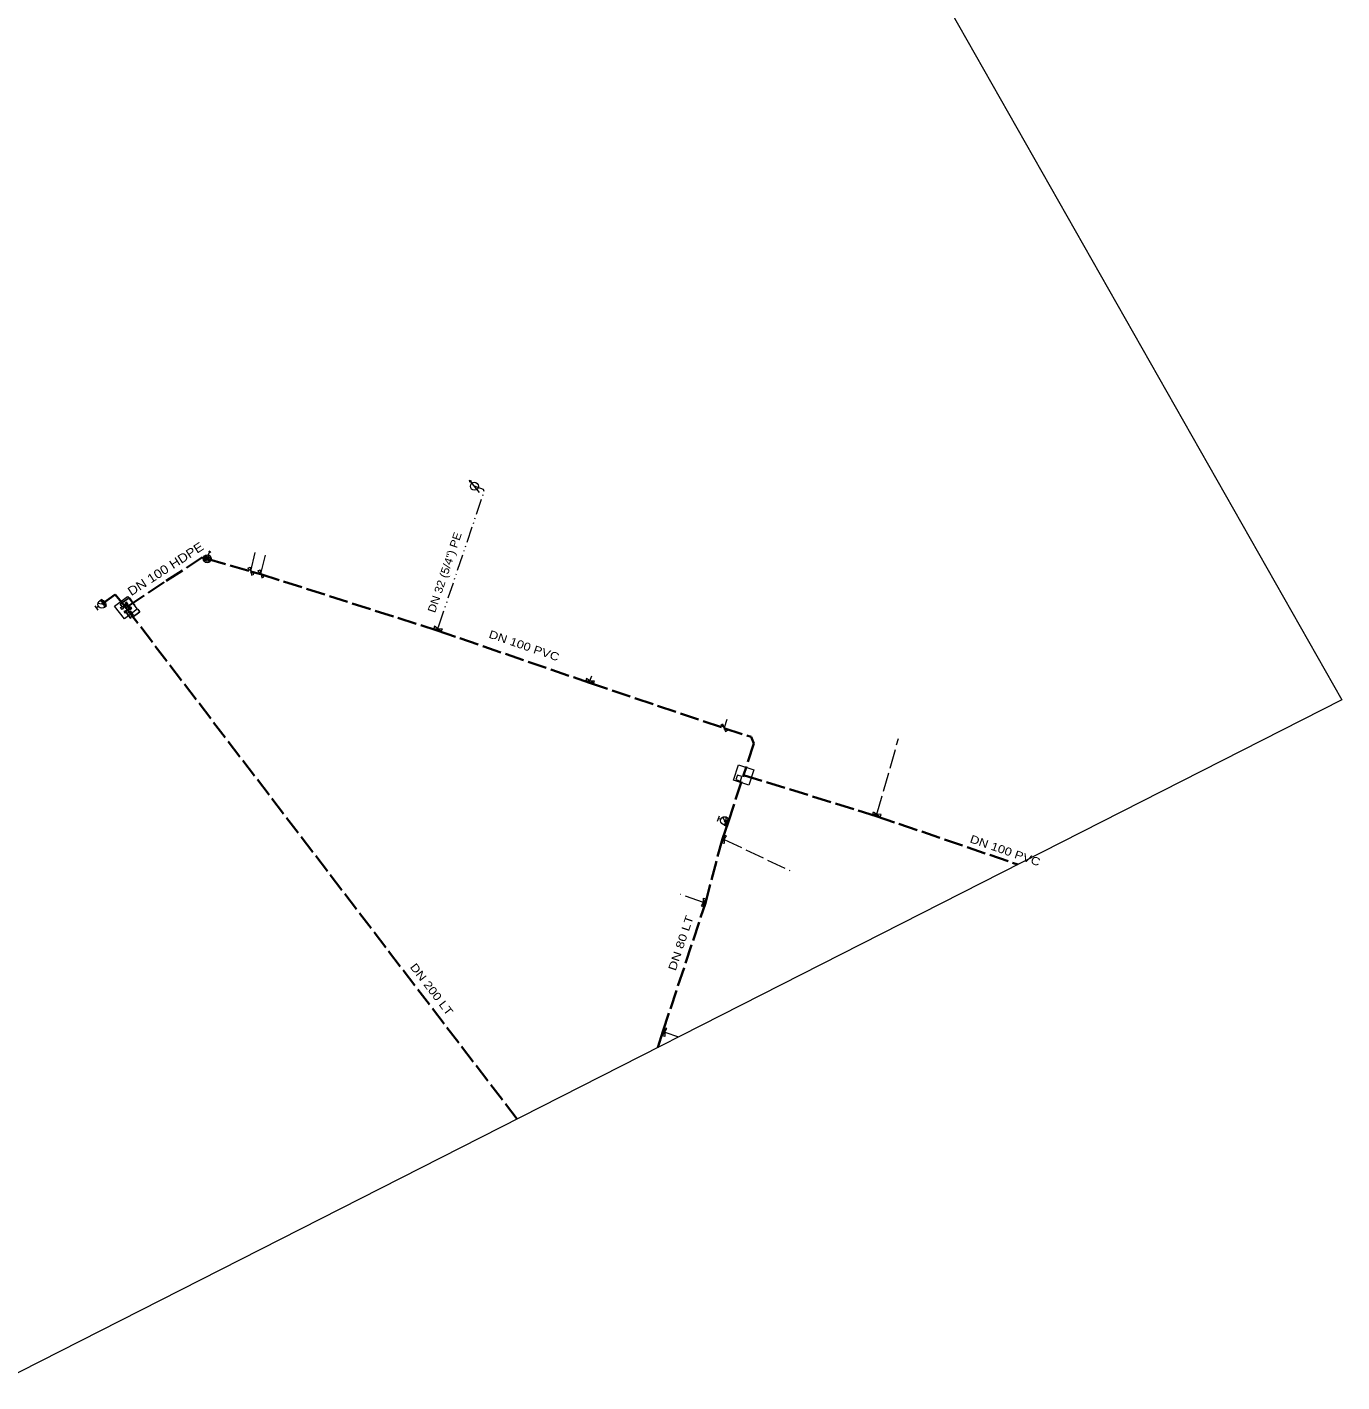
# Model space of a CAD drawing. Extents: x -666776 to -665461, y -1035476 to -1034122.
# Drawn here: x -665625.7 to -665461.4, y -1035475.8 to -1035306.5 of the extents above; entities that cross this region are included whole.
import ezdxf
from ezdxf.enums import TextEntityAlignment as Align

# ---------------------------------------------------------------- set-up
doc = ezdxf.new("R2010")
doc.units = 0
doc.header["$LTSCALE"] = 0.4
for name, pattern in [('DASH_DOUBLE_DOT', [9.2, 5, -1.2, 0.3, -1.2, 0.3, -1.2]), ('LONG_DASHED', [7.5, 6, -1.5]), ('MEDIUM_DASHED', [4.5, 3, -1.5])]:
    doc.linetypes.add(name, pattern=pattern)
for name, color, linetype, lineweight in [('1', 7, 'Continuous', 13), ('10', 7, 'Continuous', 13), ('12', 7, 'Continuous', 13), ('13', 7, 'Continuous', 13), ('21', 7, 'LONG_DASHED', 35), ('31', 7, 'LONG_DASHED', 13), ('32', 7, 'DASH_DOUBLE_DOT', 13), ('52', 7, 'MEDIUM_DASHED', 25)]:
    doc.layers.add(name, color=color, linetype=linetype, lineweight=lineweight)
doc.layers.add('29', color=7, linetype='Continuous')
doc.layers.add('39', color=7, linetype='Continuous')

msp = doc.modelspace()

# ---------------------------------------------------------------- linework, layer by layer
at = {"layer": '1'}
msp.add_lwpolyline([(-666775.826, -1034294.083), (-666679.598, -1034121.513), (-666420.972, -1034249.543), (-666137.785, -1034538.229), (-665871.094, -1034848.91), (-665670.389, -1035030.369), (-665530.17, -1035269.566), (-665461.435, -1035390.539), (-665629.148, -1035475.771), (-665736.374, -1035275.065), (-665821.605, -1035126.598), (-666206.52, -1034821.416), (-666437.468, -1034532.73), (-666634.05, -1034380.689)], close=True, dxfattribs=at)
at = {"layer": '10'}
for p, q in [((-665602.902, -1035371.968), (-665602.814, -1035372.147)), ((-665616.844, -1035379.355), (-665617.248, -1035378.784)), ((-665616.801, -1035378.896), (-665617.046, -1035379.07)), ((-665615.899, -1035378.692), (-665616.885, -1035378.523)), ((-665539.443, -1035405.715), (-665539.214, -1035405.054)), ((-665539.045, -1035405.482), (-665539.328, -1035405.385)), ((-665538.353, -1035406.096), (-665538.791, -1035405.197))]:
    msp.add_line(p, q, dxfattribs=at)
msp.add_lwpolyline([(-665603.064, -1035372.442), (-665602.902, -1035371.968), (-665603.081, -1035372.056)], dxfattribs=at)
for points in [[(-665597.416, -1035374.844), (-665598.142, -1035374.093), (-665597.875, -1035373.956), (-665597.683, -1035374.982)], [(-665596.152, -1035375.166), (-665596.893, -1035374.43), (-665596.629, -1035374.287), (-665596.416, -1035375.309)], [(-665611.988, -1035379.224), (-665613.577, -1035380.439), (-665614.792, -1035378.85), (-665613.203, -1035377.635)], [(-665615.804, -1035378.783), (-665616.625, -1035378.139), (-665616.38, -1035377.966), (-665616.049, -1035378.956)], [(-665613.271, -1035378.387), (-665613.862, -1035379.248), (-665614.05, -1035379.015), (-665613.083, -1035378.621)], [(-665613.476, -1035379.733), (-665612.866, -1035378.887), (-665612.683, -1035379.124), (-665613.659, -1035379.496)], [(-665613.501, -1035378.51), (-665612.697, -1035379.176), (-665612.946, -1035379.342), (-665613.252, -1035378.344)], [(-665574.922, -1035381.628), (-665573.879, -1035381.672), (-665573.977, -1035381.956), (-665574.823, -1035381.344)], [(-665555.922, -1035388.165), (-665554.878, -1035388.176), (-665554.967, -1035388.462), (-665555.833, -1035387.878)], [(-665538.215, -1035394.341), (-665539.062, -1035393.732), (-665538.825, -1035393.548), (-665538.452, -1035394.524)], [(-665534.937, -1035399.289), (-665535.543, -1035401.195), (-665537.449, -1035400.589), (-665536.843, -1035398.683)], [(-665519.016, -1035404.867), (-665520.059, -1035404.818), (-665519.959, -1035404.535), (-665519.115, -1035405.15)], [(-665538.362, -1035406.31), (-665538.357, -1035405.266), (-665538.07, -1035405.354), (-665538.649, -1035406.222)], [(-665538.611, -1035407.458), (-665538.629, -1035408.502), (-665538.914, -1035408.41), (-665538.325, -1035407.549)], [(-665541.199, -1035416.385), (-665541.206, -1035415.341), (-665540.918, -1035415.425), (-665541.487, -1035416.301)], [(-665546.068, -1035431.551), (-665546.043, -1035432.595), (-665546.332, -1035432.516), (-665545.778, -1035431.631)]]:
    msp.add_lwpolyline(points, close=True, dxfattribs=at)
for centre, radius in [((-665603.225, -1035372.915), 0.5), ((-665603.225, -1035372.915), 0.35), ((-665603.225, -1035372.915), 0.2), ((-665616.3933, -1035378.6075), 0.5), ((-665538.5723, -1035405.6452), 0.5)]:
    msp.add_circle(centre, radius, dxfattribs=at)
at = {"layer": '12'}
msp.add_line((-665569.215, -1035364.646), (-665570.469, -1035363.088), dxfattribs=at)
msp.add_lwpolyline([(-665570.373, -1035363.372), (-665570.469, -1035363.088), (-665570.213, -1035363.243)], dxfattribs=at)
msp.add_circle((-665569.8428, -1035363.8664), 0.5, dxfattribs=at)
at = {"layer": '13'}
for points in [[(-665612.422, -1035379.952), (-665612.768, -1035379.462), (-665613.258, -1035379.808), (-665612.912, -1035380.298)], [(-665536.402, -1035400.128), (-665536.972, -1035399.941), (-665537.159, -1035400.511), (-665536.589, -1035400.698)]]:
    msp.add_lwpolyline(points, close=True, dxfattribs=at)
at = {"layer": '21'}
for p, q in [((-665597.798, -1035374.515), (-665596.539, -1035374.845)), ((-665596.539, -1035374.845), (-665574.476, -1035381.888)), ((-665616.215, -1035378.461), (-665616.393, -1035378.607)), ((-665613.39, -1035379.037), (-665613.567, -1035378.818)), ((-665613.171, -1035379.31), (-665613.39, -1035379.037)), ((-665564.514, -1035442.924), (-665613.171, -1035379.31)), ((-665574.476, -1035381.888), (-665555.471, -1035388.41)), ((-665555.471, -1035388.41), (-665538.651, -1035394.076)), ((-665538.123, -1035405.867), (-665536.193, -1035399.939)), ((-665546.29, -1035431.989), (-665540.967, -1035415.945)), ((-665546.91, -1035433.977), (-665546.29, -1035431.989))]:
    msp.add_line(p, q, dxfattribs=at)
for points in [[(-665613.099, -1035378.843), (-665608.346, -1035375.67), (-665603.697, -1035372.669), (-665603.225, -1035372.915), (-665597.798, -1035374.515)], [(-665613.567, -1035378.818), (-665614.716, -1035377.391), (-665616.215, -1035378.461)], [(-665613.39, -1035379.037), (-665613.099, -1035378.843), (-665613.099, -1035378.843)], [(-665538.651, -1035394.076), (-665535.263, -1035395.187), (-665534.912, -1035396.009), (-665536.193, -1035399.939)], [(-665536.193, -1035399.939), (-665519.621, -1035405.079), (-665501.931, -1035411.119)], [(-665540.967, -1035415.945), (-665538.856, -1035407.898), (-665538.123, -1035405.867), (-665538.36, -1035405.788), (-665538.572, -1035405.646)]]:
    msp.add_lwpolyline(points, dxfattribs=at)
at = {"layer": '31'}
for p, q in [((-665538.856, -1035407.898), (-665538.62, -1035407.98)), ((-665538.62, -1035407.98), (-665530.41, -1035411.89)), ((-665541.203, -1035415.863), (-665544.1, -1035414.85)), ((-665540.967, -1035415.945), (-665541.203, -1035415.863)), ((-665546.29, -1035431.989), (-665546.055, -1035432.073)), ((-665546.055, -1035432.073), (-665544.333, -1035432.668))]:
    msp.add_line(p, q, dxfattribs=at)
for points in [[(-665597.798, -1035374.515), (-665597.779, -1035374.469), (-665597.125, -1035371.579)], [(-665596.539, -1035374.845), (-665596.523, -1035374.798), (-665595.792, -1035371.97)], [(-665574.476, -1035381.888), (-665574.4, -1035381.65), (-665574.284, -1035381.306)], [(-665555.471, -1035388.41), (-665555.4, -1035388.17), (-665555.182, -1035387.555)], [(-665538.303, -1035393.01), (-665538.639, -1035394.036), (-665538.651, -1035394.076)]]:
    msp.add_lwpolyline(points, dxfattribs=at)
at = {"layer": '32'}
msp.add_lwpolyline([(-665574.284, -1035381.306), (-665568.622, -1035364.533), (-665568.708, -1035364.281), (-665569.843, -1035363.866), (-665569.921, -1035363.838)], dxfattribs=at)
at = {"layer": '32', "linetype": 'LONG_DASHED'}
msp.add_lwpolyline([(-665519.621, -1035405.079), (-665519.537, -1035404.843), (-665516.843, -1035395.373)], dxfattribs=at)
at = {"layer": '52'}
msp.add_lwpolyline([(-665612.977, -1035377.781), (-665611.66, -1035379.556), (-665612.769, -1035380.379), (-665614.086, -1035378.604)], close=True, dxfattribs=at)

# ---------------------------------------------------------------- texts
at = {"layer": '29'}
for s, height, rotation, width, p in [('DN 100 HDPE', 1.1, 32.843, 1.15, (-665608.1343, -1035374.6462)), ('DN 100 PVC', 1, 341.059, 1.2, (-665563.7853, -1035384.2446)), ('DN 100 PVC', 1, 340.81, 1.2, (-665503.6704, -1035409.8425)), ('DN 80 LT', 1, 71.652, 1.25, (-665543.5665, -1035421.0814)), ('DN 200 LT', 1, 307.512, 1.2, (-665575.5781, -1035427.0235))]:
    msp.add_text(s, height=height, rotation=rotation, dxfattribs=dict(at, width=width)).set_placement(p, align=Align.CENTER)
at = {"layer": '39', "width": 1.1}
msp.add_text('DN 32 (5/4") PE', height=1, rotation=71.347, dxfattribs=at).set_placement((-665573.0821, -1035374.7749), align=Align.CENTER)

doc.saveas('drawing.dxf')
